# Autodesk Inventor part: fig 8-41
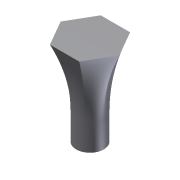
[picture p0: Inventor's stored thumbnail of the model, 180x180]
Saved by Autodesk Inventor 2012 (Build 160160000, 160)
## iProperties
Created: 2004-05
Part Number: fig 8-41
Document SubType Name: Modeling
Designer: CADCIM Technologies
Manufacturer: Standard
Standards Organization: Custom
Density: 1 g/cm^3
Material: Default
Author: CADCIM Technologies
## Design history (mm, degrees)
sketch "Sketch1"
  geometry: C1 r 16.344 at (0, 0)
  constraints: 1 centre point
extrude "Extrusion1" new body sketch "Sketch1" distance "d0" = 30.75; taper "d1" = 0 deg
workplane "Work Plane1"
sketch "Sketch2"
  geometry: L1 (34.788, 0)-(17.394, -30.128); L2 (17.394, -30.128)-(-17.394, -30.128); L3 (-17.394, -30.128)-(-34.788, 0); L4 (-34.788, 0)-(-17.394, 30.128); L5 (-17.394, 30.128)-(17.394, 30.128); L6 (17.394, 30.128)-(34.788, 0); 2 further points
  constraints: 12 end point, 1 coincident, 12 other
loft "Loft2" sketch "Sketch2" dims "d8" = 90 deg, "d9" = 0, "d10" = 90 deg, "d11" = 10
  node "Edges2"
body "Solid1"
other parameters: "d2" = 75
